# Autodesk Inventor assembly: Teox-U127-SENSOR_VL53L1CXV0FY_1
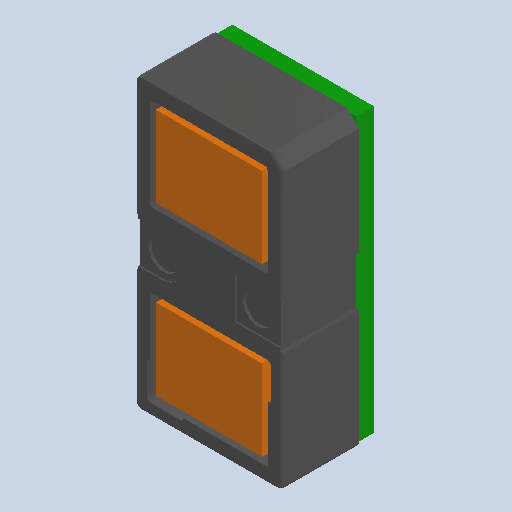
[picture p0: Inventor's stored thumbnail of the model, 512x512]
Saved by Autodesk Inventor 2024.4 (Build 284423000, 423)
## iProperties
Created: 2025-05
Part Number: Teox-U127-SENSOR_VL53L1CXV0FY_1
Document SubType Name: Assembly
Designer: AdminForWorker
Title: Teox-U127-SENSOR_VL53L1CXV0FY_1
Author: AdminForWorker
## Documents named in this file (2)
- c:\worker\convert-fusion-r02-cosv3\tmp\job-1\2\temp\files\be827049-a7f2-47ea-a815-8d9efd6bfce9\Teox-U127-SENSOR_VL53L1CXV0FY_1.iam
- c:\worker\convert-fusion-r02-cosv3\tmp\job-1\2\temp\files\be827049-a7f2-47ea-a815-8d9efd6bfce9\COMPOUND (1).ipt
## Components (1 placed, 1 different names)
1. COMPOUND (1):1
